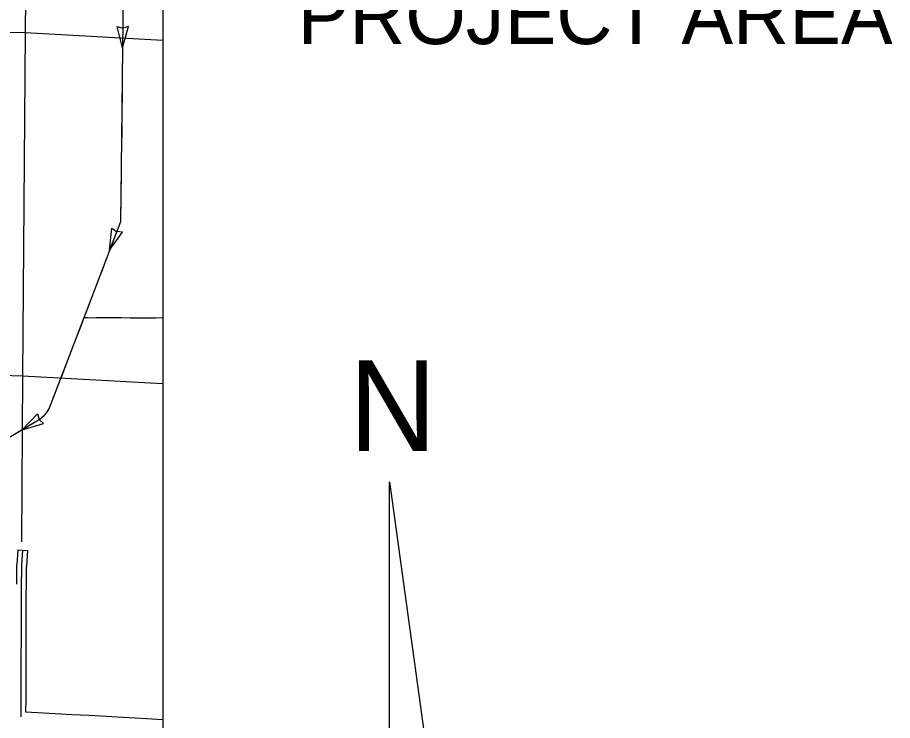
# Model space of a CAD drawing. Extents: x 1373094 to 1376427, y 1168361 to 1170494.
# Drawn here: x 1373943 to 1374169.2, y 1169815.4 to 1169997.1 of the extents above; entities that cross this region are included whole.
import ezdxf

# ---------------------------------------------------------------- set-up
doc = ezdxf.new("R2010")
doc.units = 0
for name, color, linetype in [('Default', 7, 'Continuous'), ('R_Axis', 7, 'Continuous'), ('R_Draft', 7, 'Continuous'), ('R_No Plot', 7, 'Continuous')]:
    doc.layers.add(name, color=color, linetype=linetype)

msp = doc.modelspace()

# ---------------------------------------------------------------- linework, layer by layer
at = {"layer": 'R_Axis'}
for p, q in [((1373970.19, 1169989.22), (1373968.78, 1169994.77)), ((1373968.78, 1169994.77), (1373970.24, 1169994.36)), ((1373970.19, 1169989.22), (1373971.74, 1169994.73)), ((1373971.74, 1169994.73), (1373970.26, 1169994.36)), ((1373966.86, 1169936.94), (1373967.45, 1169942.63)), ((1373966.86, 1169936.94), (1373970.21, 1169941.58)), ((1373967.45, 1169942.63), (1373968.68, 1169941.74)), ((1373970.21, 1169941.58), (1373968.7, 1169941.73)), ((1373944.26, 1169890.55), (1373948.24, 1169894.65)), ((1373948.24, 1169894.65), (1373948.66, 1169893.18)), ((1373944.26, 1169890.55), (1373949.76, 1169892.11)), ((1373949.76, 1169892.11), (1373948.67, 1169893.17)), ((1373943.11, 1169859.47), (1373945.6, 1169859.32))]:
    msp.add_line(p, q, dxfattribs=at)
for points in [[(1373945.82, 1170073.36), (1373945.04, 1169993.17), (1373944.35, 1169904.48), (1373944.12, 1169861.54)], [(1373980.59, 1170005.08), (1373978.49, 1170004.16), (1373977.56, 1170004.01), (1373970.36, 1170003.95), (1373969.77, 1169950.86), (1373969.65, 1169944.27), (1373960.22, 1169919.49), (1373951.26, 1169896.13), (1373950.81, 1169895.38), (1373950.44, 1169894.89), (1373950.18, 1169894.54), (1373949.76, 1169894.06), (1373949.42, 1169893.75), (1373948.88, 1169893.3), (1373895.65, 1169861.53), (1373894.12, 1169861.03), (1373893.46, 1169860.82), (1373892.34, 1169860.75)], [(1373970.27, 1169995.82), (1373970.19, 1169989.22)], [(1373849.78, 1169994.99), (1373858.26, 1169994.97), (1373945.04, 1169993.17), (1373980.59, 1169991.26)], [(1373970.17, 1169987.02), (1373970.13, 1169983.72)], [(1373970.13, 1169983.72), (1373970.1, 1169980.42)], [(1373970.07, 1169978.22), (1373970, 1169971.63)], [(1373969.98, 1169969.43), (1373969.9, 1169962.83)], [(1373969.88, 1169960.63), (1373969.81, 1169954.03)], [(1373969.78, 1169951.83), (1373969.77, 1169950.86), (1373969.67, 1169945.23)], [(1373969.21, 1169943.11), (1373966.86, 1169936.94)], [(1373966.08, 1169934.89), (1373964.91, 1169931.8)], [(1373964.91, 1169931.8), (1373963.73, 1169928.72)], [(1373962.95, 1169926.66), (1373960.6, 1169920.49)], [(1373959.81, 1169918.44), (1373957.45, 1169912.28)], [(1373980.59, 1169919.35), (1373960.22, 1169919.49)], [(1373961.17, 1169919.49), (1373960.22, 1169919.49)], [(1373969.97, 1169919.43), (1373963.37, 1169919.47)], [(1373975.47, 1169919.39), (1373972.17, 1169919.41)], [(1373978.77, 1169919.37), (1373975.47, 1169919.39)], [(1373956.66, 1169910.22), (1373954.3, 1169904.06)], [(1373851.81, 1169907.39), (1373857.15, 1169907.19), (1373944.35, 1169904.48), (1373980.59, 1169902.51)], [(1373953.51, 1169902), (1373951.26, 1169896.13), (1373951.1, 1169895.87)], [(1373949.8, 1169894.1), (1373949.76, 1169894.06), (1373949.42, 1169893.75), (1373948.88, 1169893.3), (1373944.26, 1169890.55)], [(1373943.11, 1169859.47), (1373942.88, 1169855.74), (1373942.79, 1169855.47), (1373942.82, 1169855.11), (1373942.78, 1169854.8), (1373942.81, 1169854.44), (1373942.8, 1169854.29), (1373942.8, 1169854.09), (1373942.76, 1169851.06), (1373942.75, 1169850.62)], [(1373944.35, 1169859.39), (1373944.12, 1169855.5), (1373944.06, 1169855.32), (1373944.08, 1169855.08), (1373944.04, 1169854.76), (1373944.06, 1169854.45), (1373944.05, 1169854.26), (1373944.05, 1169854.1), (1373944.01, 1169851.05), (1373943.99, 1169847.31)], [(1373945.6, 1169859.32), (1373945.36, 1169855.26), (1373945.33, 1169855.17), (1373945.34, 1169855.06), (1373945.29, 1169854.73), (1373945.31, 1169854.45), (1373945.3, 1169854.23), (1373945.3, 1169854.1), (1373945.26, 1169851.04), (1373945.25, 1169850.61)], [(1373945.25, 1169850.61), (1373945.24, 1169847.31), (1373945.23, 1169841.81)], [(1373943.99, 1169847.31), (1373943.97, 1169838.51)], [(1373945.23, 1169841.81), (1373945.22, 1169838.51), (1373945.2, 1169833.01)], [(1373943.97, 1169838.51), (1373943.94, 1169829.71)], [(1373945.2, 1169833.01), (1373945.19, 1169829.71), (1373945.17, 1169824.21)], [(1373943.94, 1169829.71), (1373943.91, 1169820.91)], [(1373945.17, 1169824.21), (1373945.16, 1169820.91), (1373945.15, 1169817.59)], [(1373943.91, 1169820.91), (1373943.9, 1169816.41), (1373943.9, 1169816.32)], [(1373945.15, 1169817.59), (1373952.75, 1169817.2)], [(1373952.75, 1169817.2), (1373957.1, 1169816.98), (1373961.54, 1169816.74)], [(1373961.54, 1169816.74), (1373970.33, 1169816.26)], [(1373970.33, 1169816.26), (1373975.03, 1169816), (1373979.12, 1169815.77)], [(1373979.12, 1169815.77), (1373980.59, 1169815.69)]]:
    msp.add_lwpolyline(points, dxfattribs=at)
at = {"layer": 'R_Draft'}
for p, q in [((1374039.18, 1169877.07), (1374053.73, 1169771.89)), ((1374039.18, 1169750.94), (1374039.18, 1169877.07))]:
    msp.add_line(p, q, dxfattribs=at)
at = {"layer": 'R_No Plot'}
msp.add_lwpolyline([(1373251.19, 1170420.71), (1373980.59, 1170420.71), (1373980.59, 1169636.22), (1373251.19, 1169636.22)], close=True, dxfattribs=at)

# ---------------------------------------------------------------- texts
at = {"layer": 'Default'}
msp.add_text('PROJECT AREA', height=15, dxfattribs=at).set_placement((1374015.45, 1169990.19))
at = {"layer": 'R_Draft'}
msp.add_text('N', height=23.47, dxfattribs=at).set_placement((1374028.71, 1169885.01))

doc.saveas('drawing.dxf')
